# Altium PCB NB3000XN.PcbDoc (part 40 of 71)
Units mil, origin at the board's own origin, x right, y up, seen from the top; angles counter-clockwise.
Board outline 9527.56 x 6929.77 mil, 6 copper layers (Top Layer, GND+SHIELD, MidLayer1, MidLayer2, P2 - 3V3+5V0, Bottom Layer), stack 62.375 mil thick; 832 components, 1027 nets, 4655 pads, 4981 vias.
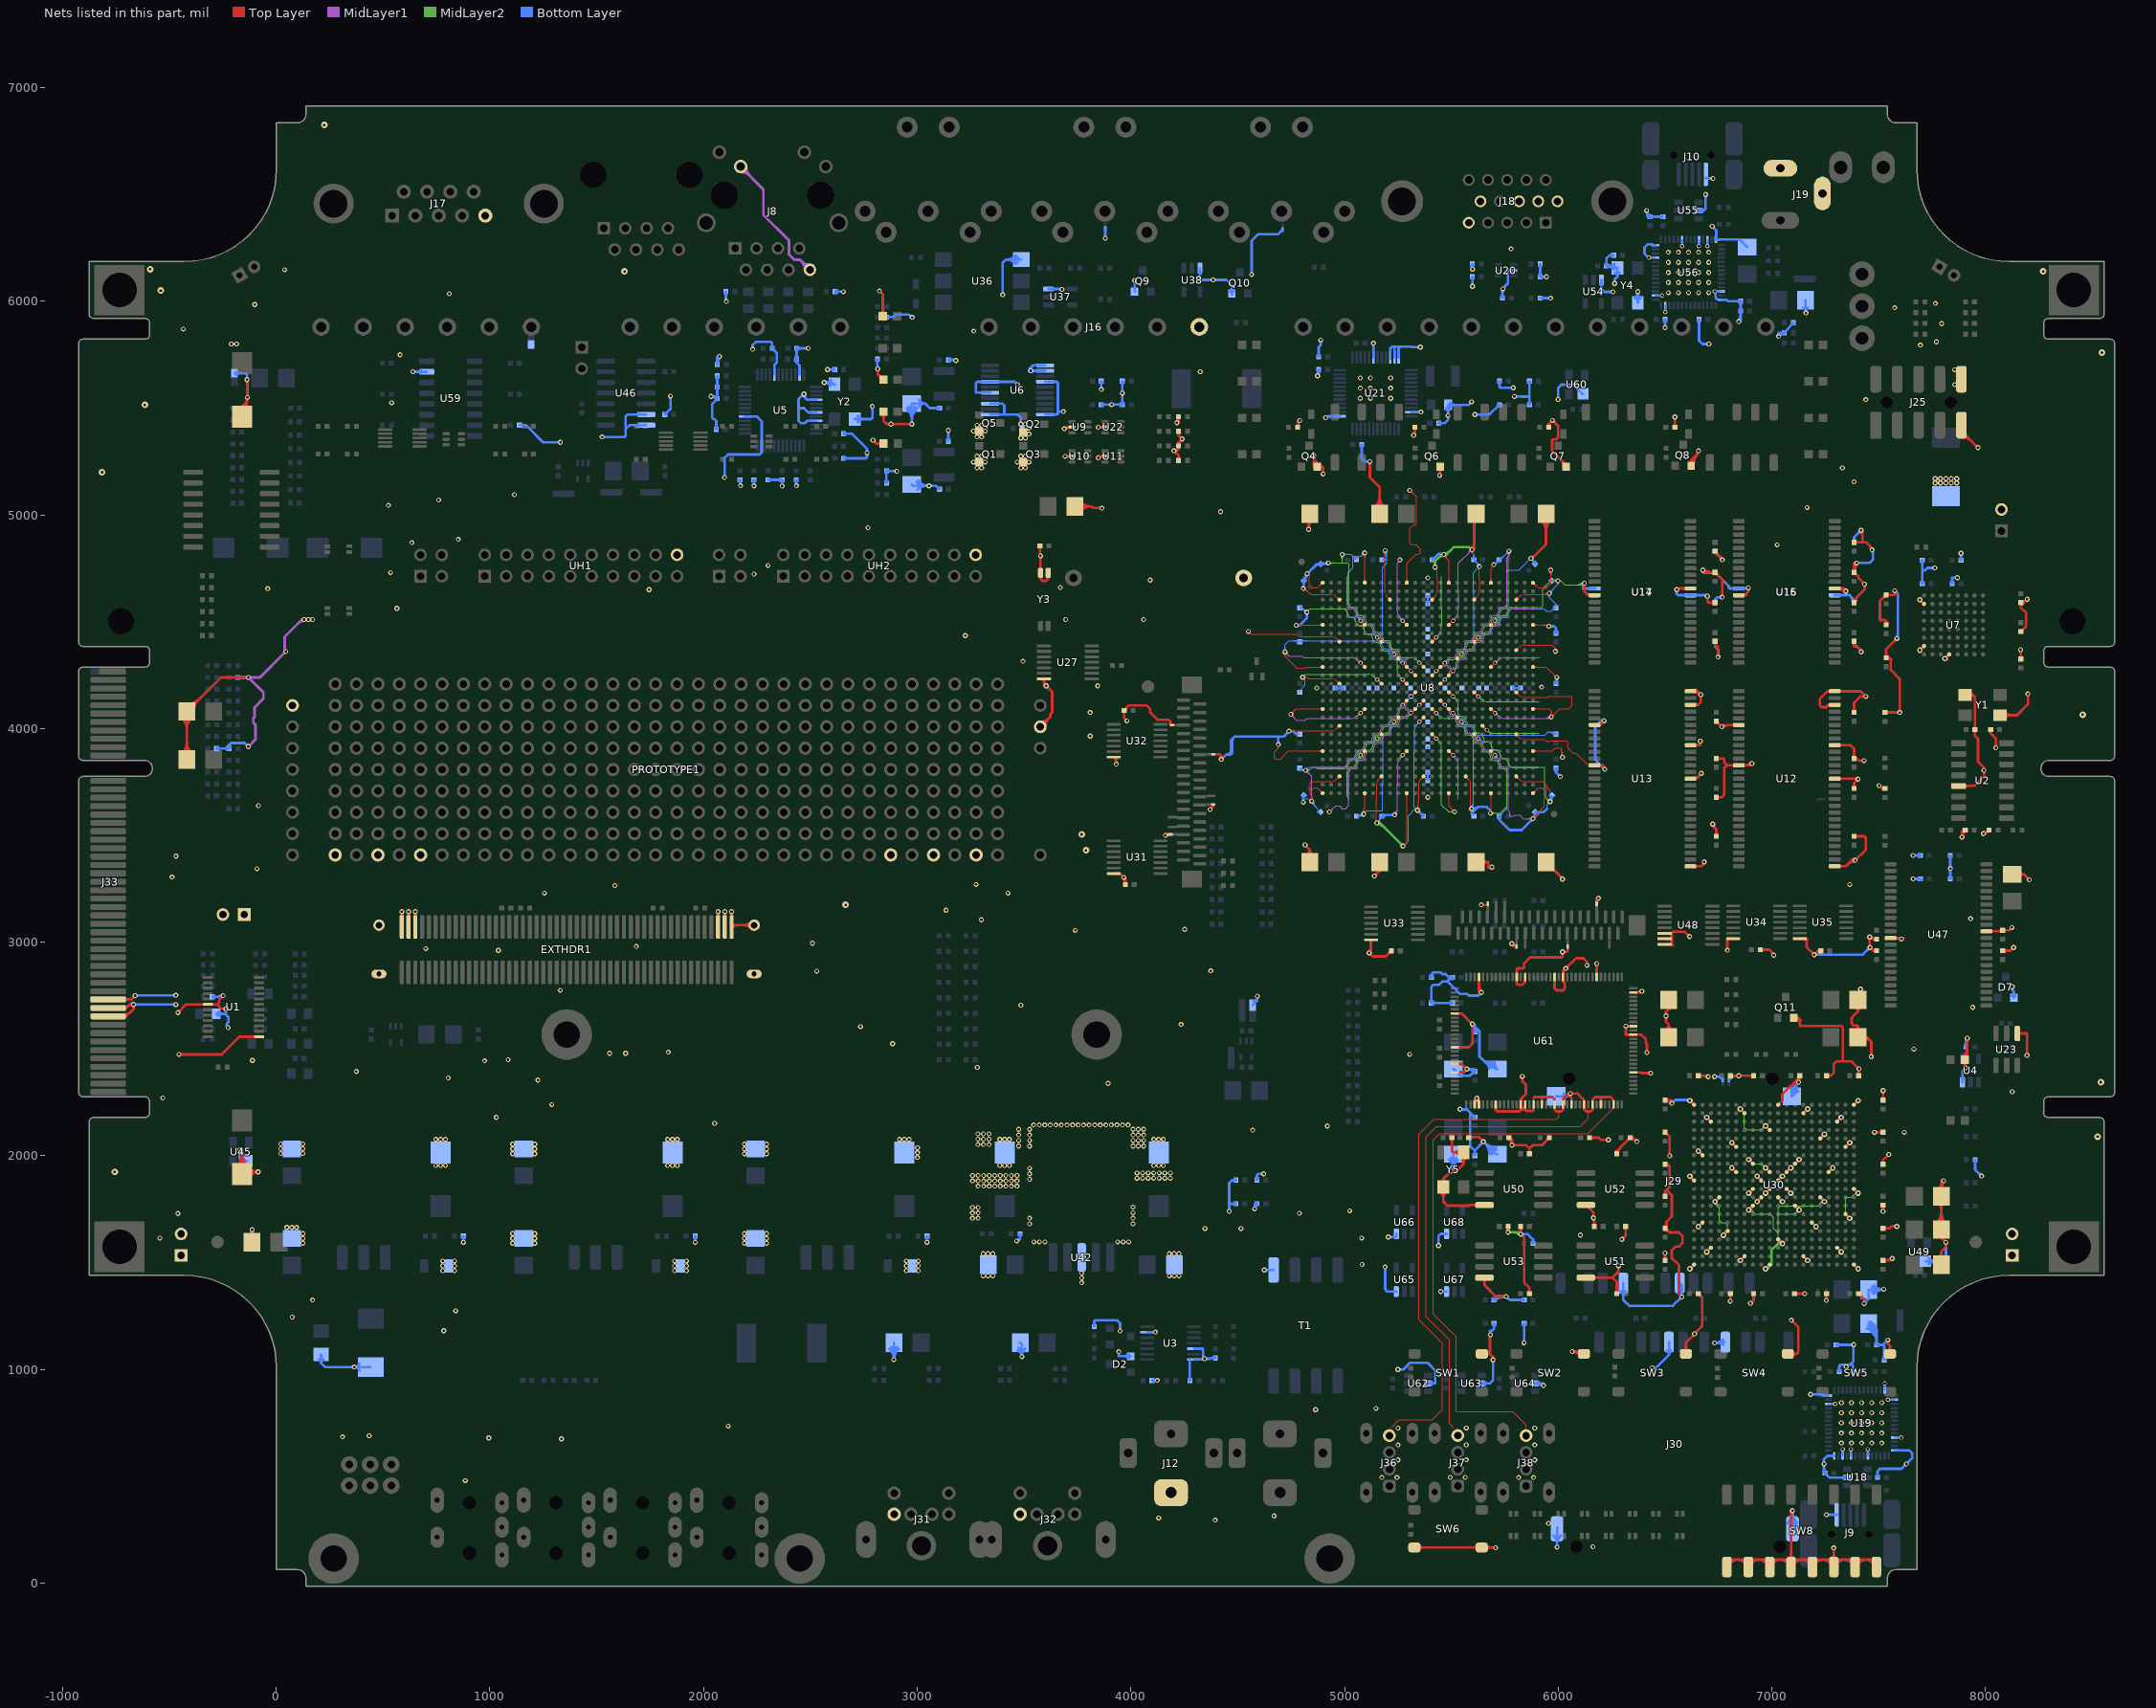
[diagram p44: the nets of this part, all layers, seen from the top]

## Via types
v1: diameter 23, hole 11.81, Top Layer to Bottom Layer, 3672 vias
v2: diameter 26, hole 11.81, Top Layer to Bottom Layer, 461 vias
v3: diameter 19, hole 11.81, Top Layer to Bottom Layer, tented both sides, 396 vias
v4: diameter 23.62, hole 11.81, Top Layer to Bottom Layer, 288 vias
v5: diameter 20, hole 11.81, Top Layer to Bottom Layer, 91 vias
v6: diameter 23, hole 11.81, Top Layer to Bottom Layer, tented both sides, 50 vias
v7: diameter 31, hole 11.81, Top Layer to Bottom Layer, 15 vias
v8: diameter 27.56, hole 11.81, Top Layer to Bottom Layer, tented both sides, 4 vias
v9: diameter 29, hole 11.81, Top Layer to Bottom Layer, 3 vias
v10: diameter 21, hole 11.81, Top Layer to Bottom Layer, 1 vias

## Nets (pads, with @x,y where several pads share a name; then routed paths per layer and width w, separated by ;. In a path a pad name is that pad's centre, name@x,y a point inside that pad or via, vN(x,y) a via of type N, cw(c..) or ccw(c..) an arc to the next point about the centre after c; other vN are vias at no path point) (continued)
GND: BT1.2 C1.2 C2.2 C3.2 C4.2 C7.2 C13.2 C18.2 C20.2 C21.2 C33.2 C34.2 C35.2 C36.2 C37.1 C39.1 C40.2 C41.1 C42.1 C43.2 C44.2 C45.1 C46.1 C47.1 C48.1 C49.2 C50.1 C51.1 C52.1 C53.1 C54.1 C55.2 C56.2 C57.2 C58.2 C59.2 C60.2 C61.2 C62.2 C63.2 C64.2 C65.2 C66.2 C67.2 C68.2 C69.2 C70.2 C71.2 C72.2 C73.2 C74.2 C75.2 C76.2 C77.2 C78.2 C79.2 C80.2 C81.2 C82.2 C83.2 C84.2 C85.2 C86.2 C87.2 C88.1 C89.2 C90.1 C91.1 C92.1 C93.2 C94.2 C95.2 C96.2 C98.2 C99.1 C100.2 C115.2 C116.2 C121.1 C122.1 C123.1 C124.1 C125.1 C126.2 C127.2 C128.2 C129.2 C130.2 C131.2 C132.2 C133.2 C134.2 C135.2 C136.2 C137.2 C138.2 C139.2 C140.2 C141.2 C151.2 C152.1 C153.2 C154.2 C155.2 C156.2 C157.1 C158.2 C159.1 C160.2 C161.1 C162.2 C163.1 C164.2 C165.1 C166.2 C167.2 C168.2 C169.1 C170.1 C171.2 C172.1 C173.1 C174.1 C175.2 C176.2 C177.2 C184.2 C185.2 C187.2 C189.2 C190.2 C191.2 C192.2 C193.2 C194.2 C195.2 C196.2 C197.2 C198.2 C199.2 C200.2 C201.2 C202.2 C203.2 C215.2 C216.2 C217.2 C218.2 C219.2 C220.2 C221.2 C222.2 C223.2 C224.2 C225.2 C226.2 C227.2 C228.2 C229.2 C231.2 C232.2 C233.2 C234.2 C235.2 C236.2 C237.2 C238.2 C239.2 C240.2 C241.2 C242.2 C243.2 C244.2 C245.2 C246.2 C247.2 C248.2 C249.2 C250.2 C251.2 C252.2 C253.2 C254.2 C255.2 C256.2 C257.2 C258.2 C259.2 C260.2 C265.2 C266.2 C267.2 C268.2 C269.2 C270.2 C271.2 C272.2 C273.2 C274.2 C275.2 C276.2 C277.2 C278.2 C279.2 C291.2 C292.2 C293.2 C294.2 C295.2 C296.2 C297.2 C298.2 C299.2 C300.2 C301.2 C302.2 C303.2 C304.2 C305.2 C307.2 C308.2 C309.2 C310.2 C311.2 C312.2 C313.2 C314.2 C315.2 C316.2 C317.2 C318.2 C319.2 C320.2 C321.2 C322.2 C323.2 C324.2 C325.2 C326.2 C327.2 C328.2 C329.2 C330.2 C331.2 C332.2 C333.2 C334.2 C335.2 C336.2 C337.2 C338.2 C339.2 C340.2 C341.2 C342.2 D2.1 D7.1 D10.1 EXTHDR1.1 EXTHDR1.3 EXTHDR1.5 EXTHDR1.95 EXTHDR1.97 EXTHDR1.99 EXTHDR1.MH1 EXTHDR1.MH2 EXTHDR1.MH3 EXTHDR1.MH4 J1.1 J1.2 J2.1 J2.2 J3.1 J3.2 J8.8 J8.10 J9.5 J10.5 J12.1 J16.6 J17.5 J18.5 J18.6 J18.7 J18.8 J18.10 J19.2 J19.3 J24.2 J25.9 J25.10 J29.3 J29.6 J29.GND1 J29.GND2 J30.3 J30.6 J30.GND1 J30.GND2 J31.3 J32.3 J33.A38 J33.A39 J33.A40 J33.B38 J36.4 J37.4 J38.4 LED1.2 LED4.2 LED5.2 LED6.2 LED7.2 NT1.2 NT4.2 NT5.2 NT7.2 NT11.2 NT28.2 NT29.2 NT30.2 NT31.2 NT38.2 NT39.2 NT40.2 NT41.2 NT44.1 NT47.1 NT48.1 PROTOTYPE1.1 PROTOTYPE1.3 PROTOTYPE1.5 PROTOTYPE1.27 PROTOTYPE1.29 PROTOTYPE1.31 Q1.3 Q2.3 Q3.3 Q4.3 Q5.3 Q6.3 Q7.3 Q8.3 Q9.3 Q10.3 Q11.3 R30.2 R34.2 R36.2 R38.1 R41.2 R42.2 R43.2 R44.2 R45.2 R46.2 R47.2 R51.2 R52.2 R56.1 R60.1 R61.2 R64.1 R65.2 R91.1 R93.1 R95.1 R97.1 R109.2 R111.2 R116.1 R117.2 R118.1 R119.2 R120.1 R121.1 R122.1 R124.1 R126.1 R128.1 R130.1 R155.1 R157.1 R160.2 R163.1 R202.2 R204.2 R206.2 R208.2 R246.2 R257.2 R258.2 R259.2 SW1.3 SW2.3 SW3.3 SW4.3 SW5.3 SW6.3 SW6.4 SW8.1 SW8.2 SW8.3 SW8.4 SW8.5 SW8.6 SW8.7 SW8.8 T1.1 TP1.1 TP8.1 U1.6 U1.13 U2.5 U3.5 U3.7 U3.13 U4.3 U5.11 U5.17 U5.29 U5.35 U5.40 U5.43 U5.45 U6.1 U6.2 U6.4 U6.10 U6.11 U6.13 U6.15 U6.17 U7.E8 U7.H2 U7.H7 U8.A1 U8.A6 U8.A11 U8.A16 U8.A21 U8.A26 U8.AA1 U8.AA6 U8.AA11 U8.AA16 U8.AA21 U8.AA26 U8.AD3 U8.AD8 U8.AD13 U8.AD18 U8.AD24 U8.AF1 U8.AF6 U8.AF11 U8.AF16 U8.AF21 U8.AF26 U8.C3 U8.C9 U8.C14 U8.C19 U8.C24 U8.F1 U8.F6 U8.F11 U8.F16 U8.F21 U8.F26 U8.H3 U8.H8 U8.H14 U8.H19 U8.J24 U8.K10 U8.K17 U8.L1 U8.L6 U8.L11 U8.L13 U8.L15 U8.L21 U8.L26 U8.M12 U8.M14 U8.M16 U8.N3 U8.N8 U8.N11 U8.N15 U8.P12 U8.P16 U8.P19 U8.P24 U8.R11 U8.R13 U8.R15 U8.T1 U8.T6 U8.T12 U8.T14 U8.T16 U8.T21 U8.T26 U8.U10 U8.U13 U8.U17 U8.V3 U8.V20 U8.W8 U8.W14 U8.W19 U8.W24 U9.2 U10.2 U11.2 U12.6 U12.12 U12.28 U12.41 U12.46 U12.52 U12.54 U13.6 U13.12 U13.28 U13.41 U13.46 U13.52 U13.54 U14.12 U14.34 U15.12 U15.34 U16.12 U16.34 U17.12 U17.34 U18.2 U19.6 U19.10 U19.12 U19.14 U19.26 U19.28 U19.41 U19.44 U19.53 U19.56 U20.2 U21.11 U21.25 U21.42 U21.46 U21.47 U21.48 U22.2 U23.1 U27.7 U30.A1 U30.A11 U30.A20 U30.B6 U30.B14 U30.C3 U30.C18 U30.D9 U30.E5 U30.E12 U30.F15 U30.G2 U30.G19 U30.H8 U30.H13 U30.J9 U30.J11 U30.K1 U30.K10 U30.K12 U30.K17 U30.L4 U30.L9 U30.L11 U30.L20 U30.M10 U30.M12 U30.N8 U30.N11 U30.N13 U30.P2 U30.P19 U30.R6 U30.R9 U30.T16 U30.U12 U30.V3 U30.V18 U30.W7 U30.W15 U30.Y1 U30.Y10 U30.Y20 U31.7 U32.7 U33.7 U34.7 U35.7 U36.4 U37.3 U38.3 U42.3 U45.1 U46.6 U46.7 U47.12 U47.34 U48.6 U48.7 U48.8 U49.1 U50.4 U51.4 U52.4 U53.4 U54.3 U55.2 U56.6 U56.10 U56.12 U56.14 U56.26 U56.28 U56.41 U56.44 U56.53 U56.56 U59.15 U60.1 U61.3 U61.4 U61.8 U61.14 U61.15 U61.17 U61.19 U61.22 U61.24 U61.26 U61.29 U61.31 U61.33 U61.36 U61.44 U61.53 U61.55 U61.63 U61.71 U61.79 U61.81 U61.88 U61.90 U61.99 U61.109 U61.117 U61.121 U61.123 U62.2 U63.2 U64.2 U65.3 U66.3 U67.3 U68.3 UH1.20 UH2.20 Y1.2 Y1.4 Y2.2 Y2.4 Y3.2 Y3.3 Y4.2 Y4.4 Y5.2 Y5.4 | length 134362.1
  Top Layer w4: v1(4550,4455) 4563.13,4441.87 4760,4441.87 4777.33,4441.87 4788.8,4430.4 4793.8,4430.4 4806,4430.4 4860,4430.4 4870,4430.4 4936.73,4430.4 cw(c4936.73,4391.72) 4964.08,4419.07 ; v1(4690.19,3925.04) 4690.19,3909.71 4672.52,3892.04 4672.52,3864.71 4678.86,3858.37 4701.52,3858.37 4737.87,3894.72 ; v1@4715.28,4350.94 cw(c4705.54,4338.69) 4721.19,4338.69 ; v1(4721.19,4358.37) 4721.19,4338.69 ; v1@4727.1,4350.94 ccw(c4736.84,4338.69) 4721.19,4338.69 ; v1(4740.19,3987.71) 4741.45,3988.97 4855.26,3988.97 4860,3988.97 4870,3988.97 4936.73,3988.97 ccw(c4936.73,4027.65) 4964.08,4000.3 ; v1(4748.52,4066.71) 4773.39,4091.57 4860,4091.57 4870,4091.57 U8.T1@4897.87,4091.57 ; v1@4748.52,4072.21 ccw(c4748.52,4085.49) 4757.91,4076.1 ccw(c4767.3,4066.71) v1@4754.02,4066.71 ; v1@4748.52,4076.21 ccw(c4748.52,4099.14) 4764.74,4082.93 ccw(c4780.96,4066.71) v1@4758.02,4066.71 ; v1(4773.52,4483.37) 4775.43,4485.28 4860,4485.28 4870,4485.28 U8.F1@4897.87,4485.28 ; 4774.72,3894.72 4737.87,3894.72 ; v1@4777.41,4479.49 cw(c4791.39,4465.51) 4791.39,4485.28 ; v1@4780.24,4476.66 cw(c4801.05,4455.85) 4801.05,4485.28 ; v1@4780.24,4490.09 ccw(c4791.87,4501.72) 4791.87,4485.28 ; v1@4807,4645.5 cw(c4807,4604.3) 4836.13,4633.43 ; v1@4807,4649.5 cw(c4807,4617.96) 4829.3,4640.26 ; v1@4807,4653.5 cw(c4807,4631.62) 4822.47,4647.09 ; v1(4807,4655) 4808.85,4656.85 4812.71,4656.85 4842.19,4627.37 4842.19,4627.25 4855.26,4627.25 4860,4627.25 4870,4627.25 4936.73,4627.25 ; v1@4810.69,4233.55 v1(4803.86,4240.37) 4823.17,4240.37 4830,4233.55 4855.26,4233.55 4860,4233.55 4870,4233.55 4936.73,4233.55 cw(c4936.73,4194.87) 4964.08,4222.22 ; v1(4825.19,4725.04) 4835,4715.23 4835,4670 4846.74,4658.26 4856.86,4658.26 ; v1@4839.47,3666.76 ccw(c4823.26,3682.98) 4846.19,3682.98 ccw(c4869.13,3682.98) v1@4852.91,3666.76 ; 4840,3715 4840,3718.47 ; v1@4842.3,3663.93 ccw(c4832.91,3673.32) 4846.19,3673.32 ccw(c4859.47,3673.32) v1@4850.08,3663.93 ; v1(4846.19,3660.04) 4846.19,3683.81 4840,3690 4840,3718.47 ; 4857.99,4658.26 ccw(c4857.99,4696.94) 4885.34,4669.59 ; U8.AF1@4890.53,3697.87 ccw(c4872.8,3697.87) 4885.34,3710.41 ; U8.A1@4890.53,4682.13 cw(c4872.8,4682.13) 4885.34,4669.59 ; U8.AA1@4892.57,3889.42 ccw(c4879.77,3876.62) 4879.77,3894.72 ccw(c4879.77,3912.83) U8.AA1@4892.57,3900.03 ; U8.T1@4892.57,4086.27 ccw(c4879.77,4073.47) 4879.77,4091.57 ccw(c4879.77,4109.68) U8.T1@4892.57,4096.88 ; U8.L1@4892.57,4283.12 ccw(c4879.77,4270.32) 4879.77,4288.43 ccw(c4879.77,4306.53) U8.L1@4892.57,4293.73 ; U8.F1@4892.57,4479.97 ccw(c4879.77,4467.17) 4879.77,4485.28 ccw(c4879.77,4503.38) U8.F1@4892.57,4490.58 ; U8.AA1@4892.68,3889.53 ccw(c4880.15,3877) 4880.15,3894.72 ccw(c4880.15,3912.45) U8.AA1@4892.68,3899.92 ; U8.T1@4892.68,4086.38 ccw(c4880.15,4073.85) 4880.15,4091.57 ccw(c4880.15,4109.3) U8.T1@4892.68,4096.77 ; U8.L1@4892.68,4283.23 ccw(c4880.15,4270.7) 4880.15,4288.43 ccw(c4880.15,4306.15) U8.L1@4892.68,4293.62 ; U8.F1@4892.68,4480.08 ccw(c4880.15,4467.55) 4880.15,4485.28 ccw(c4880.15,4503) U8.F1@4892.68,4490.47 ; U8.AF1@4897.87,3705.22 cw(c4897.87,3722.94) 4885.34,3710.41 ; U8.AA1@4897.87,3894.72 4870,3894.72 4860,3894.72 4737.87,3894.72 ; U8.L1@4897.87,4288.43 4870,4288.43 4860,4288.43 4823.43,4288.43 4817.54,4282.54 4777.34,4282.54 4721.19,4338.69 ; U8.A1@4897.87,4674.78 ccw(c4897.87,4657.06) 4885.34,4669.59 ; U8.AD3@4969.27,3776.61 cw(c4951.55,3776.61) 4964.08,3764.08 ; U8.V3@4969.27,4012.83 cw(c4951.55,4012.83) 4964.08,4000.3 ; U8.N3@4969.27,4209.69 ccw(c4951.55,4209.69) 4964.08,4222.22 ; U8.H3@4969.27,4406.54 ccw(c4951.55,4406.54) 4964.08,4419.07 ; U8.C3@4969.27,4603.39 ccw(c4951.55,4603.39) 4964.08,4615.92 ; U8.AD3@4976.61,3769.27 ccw(c4976.61,3751.55) 4964.08,3764.08 ; U8.V3@4976.61,4005.49 ccw(c4976.61,3987.77) 4964.08,4000.3 ; U8.N3@4976.61,4217.03 cw(c4976.61,4234.75) 4964.08,4222.22 ; U8.H3@4976.61,4413.88 cw(c4976.61,4431.6) 4964.08,4419.07 ; U8.C3@4976.61,4610.73 cw(c4976.61,4628.45) 4964.08,4615.92 ; v3(5075.04,3875.04) U8.AA6@5094.72,3894.72 ; v3(5075.04,4071.89) U8.T6@5094.72,4091.57 ; v3(5075.04,4308.11) U8.L6@5094.72,4288.43 ; v3(5075.04,4504.96) U8.F6@5094.72,4485.28 ; v1@5083.47,3606.76 ccw(c5067.71,3622.52) 5090,3622.52 ; v1@5086.3,3603.93 ccw(c5077.37,3612.86) 5090,3612.86 ; U8.AA6@5087.22,3894.72 cw(c5069.12,3894.72) 5081.92,3881.92 cw(c5094.72,3869.12) U8.AA6@5094.72,3887.22 ; U8.T6@5087.22,4091.57 cw(c5069.12,4091.57) 5081.92,4078.77 cw(c5094.72,4065.97) U8.T6@5094.72,4084.07 ; U8.L6@5087.22,4288.43 ccw(c5069.12,4288.43) 5081.92,4301.23 ccw(c5094.72,4314.03) U8.L6@5094.72,4295.93 ; U8.F6@5087.22,4485.28 ccw(c5069.12,4485.28) 5081.92,4498.08 ccw(c5094.72,4510.88) U8.F6@5094.72,4492.78 ; U8.AA6@5087.38,3894.72 cw(c5069.66,3894.72) 5082.19,3882.19 cw(c5094.72,3869.66) U8.AA6@5094.72,3887.38 ; U8.T6@5087.38,4091.57 cw(c5069.66,4091.57) 5082.19,4079.04 cw(c5094.72,4066.51) U8.T6@5094.72,4084.23 ; U8.L6@5087.38,4288.43 ccw(c5069.66,4288.43) 5082.19,4300.96 ccw(c5094.72,4313.49) U8.L6@5094.72,4295.77 ; U8.F6@5087.38,4485.28 ccw(c5069.66,4485.28) 5082.19,4497.81 ccw(c5094.72,4510.34) U8.F6@5094.72,4492.62 ; v1@5087.81,4815.66 cw(c5071.11,4798.96) 5094.72,4798.96 ; U8.AF6@5089.42,3692.57 cw(c5076.62,3679.77) 5094.72,3679.77 cw(c5112.83,3679.77) U8.AF6@5100.03,3692.57 ; U8.A6@5089.42,4687.43 ccw(c5076.62,4700.23) 5094.72,4700.23 ccw(c5112.83,4700.23) U8.A6@5100.03,4687.43 ; U8.AF6@5089.53,3692.68 cw(c5077,3680.15) 5094.72,3680.15 cw(c5112.45,3680.15) U8.AF6@5099.92,3692.68 ; U8.A6@5089.53,4687.32 ccw(c5077,4699.85) 5094.72,4699.85 ccw(c5112.45,4699.85) U8.A6@5099.92,4687.32 ; 5090,3613.78 ccw(c5103.93,3613.78) v1@5094.08,3603.93 ; 5090,3623.43 ccw(c5113.58,3623.43) v1@5096.91,3606.76 ; v1@5090.64,4818.49 cw(c5080.76,4808.61) 5094.72,4808.61 ; v1(5094.52,4822.37) 5094.72,4822.17 5094.72,4724.74 5094.72,4720 5094.72,4710 U8.A6@5094.72,4682.13 ; v1@5094.72,3604.57 v1(5090.19,3600.04) 5090,3600.23 5090,3625 5094.72,3629.72 5094.72,3660 5094.72,3670 U8.AF6@5094.72,3697.87 ; 5094.72,4799.92 cw(c5116.98,4799.92) v1@5101.24,4815.66 ; 5094.72,4809.58 cw(c5107.32,4809.58) v1@5098.41,4818.49 ; U33.7@5123.52,3011.46 U33.7@5125,3011.46 ; v1(5150.86,3558.37) 5149.6,3559.63 5149.6,3655.26 5149.6,3660 5149.6,3670 5149.6,3736.73 cw(c5188.28,3736.73) 5160.93,3764.08 ; v3(5153.78,3953.78) U8.W8@5173.46,3973.46 ; v3(5153.78,4229.37) U8.N8@5173.46,4209.69 ; v3(5153.78,4426.22) U8.H8@5173.46,4406.54 ; U8.W8@5165.96,3973.46 cw(c5147.86,3973.46) 5160.66,3960.66 cw(c5173.46,3947.86) U8.W8@5173.46,3965.96 ; U8.N8@5165.96,4209.69 ccw(c5147.86,4209.69) 5160.66,4222.49 ccw(c5173.46,4235.29) U8.N8@5173.46,4217.19 ; U8.H8@5165.96,4406.54 ccw(c5147.86,4406.54) 5160.66,4419.34 ccw(c5173.46,4432.14) U8.H8@5173.46,4414.04 ; U8.AD8@5166.12,3776.61 cw(c5148.4,3776.61) 5160.93,3764.08 ; U8.W8@5166.12,3973.46 cw(c5148.4,3973.46) 5160.93,3960.93 cw(c5173.46,3948.4) U8.W8@5173.46,3966.12 ; U8.N8@5166.12,4209.69 ccw(c5148.4,4209.69) 5160.93,4222.22 ccw(c5173.46,4234.75) U8.N8@5173.46,4217.03 ; U8.H8@5166.12,4406.54 ccw(c5148.4,4406.54) 5160.93,4419.07 ccw(c5173.46,4431.6) U8.H8@5173.46,4413.88 ; U8.AD8@5173.46,3769.27 ccw(c5173.46,3751.55) 5160.93,3764.08 ; v1(5190.19,4833.37) 5190.19,4825.04 5188.97,4823.82 5188.97,4724.74 5188.97,4720 5188.97,4710 5188.97,4643.27 ccw(c5227.65,4643.27) 5200.3,4615.92 ; U8.C9@5205.49,4603.39 ccw(c5187.77,4603.39) 5200.3,4615.92 ; U8.C9@5212.83,4610.73 cw(c5212.83,4628.45) 5200.3,4615.92 ; v3(5232.52,4032.52) U8.U10@5252.2,4052.2 ; v3(5232.52,4347.48) U8.K10@5252.2,4327.8 ; U8.U10@5244.7,4052.2 cw(c5226.6,4052.2) 5239.4,4039.4 cw(c5252.2,4026.6) U8.U10@5252.2,4044.7 ; U8.K10@5244.7,4327.8 ccw(c5226.6,4327.8) 5239.4,4340.6 ccw(c5252.2,4353.4) U8.K10@5252.2,4335.3 ; U8.U10@5244.86,4052.2 cw(c5227.14,4052.2) 5239.67,4039.67 cw(c5252.2,4027.14) U8.U10@5252.2,4044.86 ; U8.K10@5244.86,4327.8 ccw(c5227.14,4327.8) 5239.67,4340.33 ccw(c5252.2,4352.86) U8.K10@5252.2,4335.14 ; v3(5271.89,3875.04) U8.AA11@5291.57,3894.72 ; v3(5271.89,4111.26) U8.R11@5291.57,4130.94 ; v3(5271.89,4229.37) U8.N11@5291.57,4209.69 ; v3(5271.89,4308.11) U8.L11@5291.57,4288.43 ; v3(5271.89,4504.96) U8.F11@5291.57,4485.28 ; v1(5273.52,3450.04) 5279.19,3450.04 5291.58,3462.43 ; v1@5275.34,3455.23 ccw(c5279.06,3465.92) 5287.07,3457.92 ; v1@5276.65,3459.01 ccw(c5281.39,3472.61) 5291.57,3462.43 ; v1@5283.02,3450.04 cw(c5292.28,3450.04) 5285.74,3456.59 ; U8.AA11@5284.07,3894.72 cw(c5265.97,3894.72) 5278.77,3881.92 cw(c5291.57,3869.12) U8.AA11@5291.57,3887.22 ; U8.R11@5284.07,4130.94 cw(c5265.97,4130.94) 5278.77,4118.14 cw(c5291.57,4105.34) U8.R11@5291.57,4123.44 ; U8.N11@5284.07,4209.69 ccw(c5265.97,4209.68) 5278.77,4222.49 ccw(c5291.57,4235.29) U8.N11@5291.57,4217.19 ; U8.L11@5284.07,4288.43 ccw(c5265.97,4288.43) 5278.77,4301.23 ccw(c5291.57,4314.03) U8.L11@5291.57,4295.93 ; U8.F11@5284.07,4485.28 ccw(c5265.97,4485.28) 5278.77,4498.08 ccw(c5291.57,4510.88) U8.F11@5291.57,4492.78 ; U8.AA11@5284.23,3894.72 cw(c5266.51,3894.72) 5279.04,3882.19 cw(c5291.57,3869.66) U8.AA11@5291.57,3887.38 ; U8.R11@5284.23,4130.94 cw(c5266.51,4130.94) 5279.04,4118.41 cw(c5291.57,4105.88) U8.R11@5291.57,4123.6 ; U8.N11@5284.23,4209.69 ccw(c5266.51,4209.68) 5279.04,4222.22 ccw(c5291.57,4234.75) U8.N11@5291.57,4217.03 ; U8.L11@5284.23,4288.43 ccw(c5266.51,4288.43) 5279.04,4300.96 ccw(c5291.57,4313.49) U8.L11@5291.57,4295.77 ; U8.F11@5284.23,4485.28 ccw(c5266.51,4485.28) 5279.04,4497.81 ccw(c5291.57,4510.34) U8.F11@5291.57,4492.62 ; U8.AF11@5286.27,3692.57 cw(c5273.47,3679.77) 5291.57,3679.77 cw(c5309.68,3679.77) U8.AF11@5296.88,3692.57 ; U8.A11@5286.27,4687.43 ccw(c5273.47,4700.23) 5291.57,4700.23 ccw(c5309.68,4700.23) U8.A11@5296.88,4687.43 ; U8.AF11@5286.38,3692.68 cw(c5273.85,3680.15) 5291.57,3680.15 cw(c5309.3,3680.15) U8.AF11@5296.77,3692.68 ; U8.A11@5286.38,4687.32 ccw(c5273.85,4699.85) 5291.57,4699.85 ccw(c5309.3,4699.85) U8.A11@5296.77,4687.32 ; U8.AF11@5291.57,3697.87 5291.57,3670 5291.57,3660 5291.57,3655.26 5291.58,3462.43 ; U8.A11@5291.57,4682.13 5291.57,4710 5291.57,4720 5291.57,4772.78 5333.8,4815 5347.02,4815 5355.5,4823.48 5355.5,4838.42 5351.96,4841.96 5345,4848.92 5333.92,4860 5315,4860 5306.02,4868.98 5306.02,4936.02 5325.69,4955.69 5332.17,4955.69 5336.48,4960 5336.48,5083.52 v4(5305,5115) ; v4@5305,5105.19 cw(c5305,5081.5) 5321.75,5098.25 cw(c5338.5,5115) v4@5314.81,5115 ; v4@5305,5109.19 cw(c5305,5095.16) 5314.92,5105.08 cw(c5324.84,5115) v4@5310.81,5115 ; v3(5311.26,4071.89) U8.T12@5330.94,4091.57 ; v3(5311.26,4150.63) U8.P12@5330.94,4170.31 ; v3(5311.26,4268.74) U8.M12@5330.94,4249.06 ; U8.T12@5323.44,4091.57 cw(c5305.34,4091.57) 5318.14,4078.77 cw(c5330.94,4065.97) U8.T12@5330.94,4084.07 ; U8.P12@5323.44,4170.32 cw(c5305.34,4170.32) 5318.14,4157.51 cw(c5330.94,4144.71) U8.P12@5330.94,4162.81 ; U8.M12@5323.44,4249.06 ccw(c5305.34,4249.06) 5318.14,4261.86 ccw(c5330.94,4274.66) U8.M12@5330.94,4256.56 ; U8.T12@5323.6,4091.57 cw(c5305.88,4091.57) 5318.41,4079.04 cw(c5330.94,4066.51) U8.T12@5330.94,4084.23 ; U8.P12@5323.6,4170.32 cw(c5305.88,4170.32) 5318.41,4157.78 cw(c5330.94,4145.25) U8.P12@5330.94,4162.97 ; U8.M12@5323.6,4249.06 ccw(c5305.88,4249.06) 5318.41,4261.59 ccw(c5330.94,4274.12) U8.M12@5330.94,4256.4 ; v1@5335.02,3624.97 ccw(c5310.24,3651.37) 5346.45,3651.37 ; v1@5337.76,3622.05 ccw(c5318.91,3642.13) 5346.45,3642.13 ; v1@5340.5,3619.13 ccw(c5327.58,3632.89) 5346.45,3632.89 ; v1(5341.52,3618.04) 5346.45,3622.97 5346.45,3651.37 ; 5346.45,3629.08 ccw(c5352.56,3629.08) v1@5348.24,3624.76 ; v3(5350.63,4032.52) U8.U13@5370.31,4052.2 ; v3(5350.63,4111.26) U8.R13@5370.31,4130.94 ; v3(5350.63,4308.11) U8.L13@5370.31,4288.43 ; U8.U13@5362.81,4052.2 cw(c5344.71,4052.2) 5357.51,4039.4 cw(c5370.31,4026.6) U8.U13@5370.31,4044.7 ; U8.R13@5362.81,4130.94 cw(c5344.71,4130.94) 5357.51,4118.14 cw(c5370.31,4105.34) U8.R13@5370.31,4123.44 ; U8.L13@5362.81,4288.43 ccw(c5344.71,4288.43) 5357.51,4301.23 ccw(c5370.31,4314.03) U8.L13@5370.31,4295.93 ; U8.AD13@5362.97,3776.61 cw(c5345.25,3776.61) 5357.78,3764.08 ; U8.U13@5362.97,4052.2 cw(c5345.25,4052.2) 5357.78,4039.67 cw(c5370.31,4027.14) U8.U13@5370.31,4044.86 ; U8.R13@5362.97,4130.94 cw(c5345.25,4130.94) 5357.78,4118.41 cw(c5370.31,4105.88) U8.R13@5370.31,4123.6 ; U8.L13@5362.97,4288.43 ccw(c5345.25,4288.43) 5357.78,4300.96 ccw(c5370.31,4313.49) U8.L13@5370.31,4295.77 ; U8.AD13@5370.31,3769.27 ccw(c5370.31,3751.55) 5357.78,3764.08 ; U8.W14@5409.69,3965.96 cw(c5409.69,3947.86) 5422.49,3960.66 cw(c5435.29,3973.46) U8.W14@5417.19,3973.46 ; U8.W14@5409.69,3966.12 cw(c5409.69,3948.4) 5422.22,3960.93 cw(c5434.75,3973.46) U8.W14@5417.03,3973.46 ; U8.W14@5409.69,3973.46 v3(5429.37,3953.78) ; U8.T14@5409.69,4084.07 cw(c5409.69,4065.97) 5422.49,4078.77 cw(c5435.29,4091.57) U8.T14@5417.19,4091.57 ; U8.T14@5409.69,4084.23 cw(c5409.69,4066.51) 5422.22,4079.04 cw(c5434.75,4091.57) U8.T14@5417.03,4091.57 ; U8.T14@5409.69,4091.57 v3(5429.37,4071.89) ; U8.M14@5409.69,4249.06 v3(5429.37,4268.74) ; U8.M14@5409.69,4256.4 ccw(c5409.69,4274.12) 5422.22,4261.59 ccw(c5434.75,4249.06) U8.M14@5417.03,4249.06 ; U8.M14@5409.69,4256.56 ccw(c5409.69,4274.66) 5422.49,4261.86 ccw(c5435.29,4249.06) U8.M14@5417.19,4249.06 ; U8.H14@5409.69,4406.54 v3(5429.37,4426.22) ; U8.H14@5409.69,4413.88 ccw(c5409.69,4431.6) 5422.22,4419.07 ccw(c5434.75,4406.54) U8.H14@5417.03,4406.54 ; U8.H14@5409.69,4414.04 ccw(c5409.69,4432.14) 5422.49,4419.34 ccw(c5435.29,4406.54) U8.H14@5417.19,4406.54 ; U8.C14@5409.69,4610.73 ccw(c5409.69,4628.45) 5422.22,4615.92 ; U8.C14@5417.03,4603.39 cw(c5434.75,4603.39) 5422.22,4615.92 ; v1(5423.52,4755.71) 5433.55,4745.68 5433.55,4720 5433.55,4710 5433.55,4643.27 cw(c5394.87,4643.27) 5422.22,4615.92 ; 5433.55,4724.74 5433.55,4725.04 ; U8.R15@5449.06,4123.44 cw(c5449.06,4105.34) 5461.86,4118.14 cw(c5474.66,4130.94) U8.R15@5456.56,4130.94 ; U8.R15@5449.06,4123.6 cw(c5449.06,4105.88) 5461.59,4118.41 cw(c5474.12,4130.94) U8.R15@5456.4,4130.94 ; U8.R15@5449.06,4130.94 v3(5468.74,4111.26) ; U8.N15@5449.06,4209.69 v3(5468.74,4229.37) ; U8.N15@5449.06,4217.03 ccw(c5449.06,4234.75) 5461.59,4222.22 ccw(c5474.12,4209.68) U8.N15@5456.4,4209.69 ; U8.N15@5449.06,4217.19 ccw(c5449.06,4235.29) 5461.86,4222.49 ccw(c5474.66,4209.68) U8.N15@5456.56,4209.69 ; U8.L15@5449.06,4288.43 v3(5468.74,4308.11) ; U8.L15@5449.06,4295.77 ccw(c5449.06,4313.49) 5461.59,4300.96 ccw(c5474.12,4288.43) U8.L15@5456.4,4288.43 ; U8.L15@5449.06,4295.93 ccw(c5449.06,4314.03) 5461.86,4301.23 ccw(c5474.66,4288.43) U8.L15@5456.56,4288.43 ; v1@5465,4805.5 cw(c5465,4798.1) 5470.23,4803.33 ; v1(5465,4815) 5458.56,4815 5488.43,4785.14 5488.43,4724.74 5488.43,4720 5488.43,4710 U8.A16@5488.43,4682.13 ; v1@5466.5,4814.97 ccw(c5484.84,4814.67) 5471.87,4801.7 ; v1@5470.5,4814.91 ccw(c5497.95,4814.44) 5478.54,4795.03 ; v1@5474.5,4814.84 ccw(c5511.07,4814.22) 5485.21,4788.36 ; U8.AF16@5483.12,3692.57 cw(c5470.32,3679.77) 5488.43,3679.77 cw(c5506.53,3679.77) U8.AF16@5493.73,3692.57 ; U8.A16@5483.12,4687.43 ccw(c5470.32,4700.23) 5488.43,4700.23 ccw(c5506.53,4700.23) U8.A16@5493.73,4687.43 ; U8.AF16@5483.23,3692.68 cw(c5470.7,3680.15) 5488.43,3680.15 cw(c5506.15,3680.15) U8.AF16@5493.62,3692.68 ; U8.A16@5483.23,4687.32 ccw(c5470.7,4699.85) 5488.43,4699.85 ccw(c5506.15,4699.85) U8.A16@5493.62,4687.32 ; U8.AF16@5488.43,3697.87 5488.43,3670 5488.43,3660 5488.43,3655.26 5488.43,3637.81 v1@5515.62,3610.62 ; U8.AA16@5488.43,3887.22 cw(c5488.43,3869.12) 5501.23,3881.92 cw(c5514.03,3894.72) U8.AA16@5495.93,3894.72 ; U8.AA16@5488.43,3887.38 cw(c5488.43,3869.66) 5500.96,3882.19 cw(c5513.49,3894.72) U8.AA16@5495.77,3894.72 ; U8.AA16@5488.43,3894.72 v3(5508.11,3875.04) ; U8.T16@5488.43,4084.07 cw(c5488.43,4065.97) 5501.23,4078.77 cw(c5514.03,4091.57) U8.T16@5495.93,4091.57 ; U8.T16@5488.43,4084.23 cw(c5488.43,4066.51) 5500.96,4079.04 cw(c5513.49,4091.57) U8.T16@5495.77,4091.57 ; U8.T16@5488.43,4091.57 v3(5508.11,4071.89) ; U8.P16@5488.43,4162.81 cw(c5488.43,4144.71) 5501.23,4157.51 cw(c5514.03,4170.32) U8.P16@5495.93,4170.32 ; U8.P16@5488.43,4162.97 cw(c5488.43,4145.25) 5500.96,4157.78 cw(c5513.49,4170.32) U8.P16@5495.77,4170.32 ; U8.P16@5488.43,4170.31 v3(5508.11,4150.63) ; U8.M16@5488.43,4249.06 v3(5508.11,4268.74) ; U8.M16@5488.43,4256.4 ccw(c5488.43,4274.12) 5500.96,4261.59 ccw(c5513.49,4249.06) U8.M16@5495.77,4249.06 ; U8.M16@5488.43,4256.56 ccw(c5488.43,4274.66) 5501.23,4261.86 ccw(c5514.03,4249.06) U8.M16@5495.93,4249.06 ; U8.F16@5488.43,4485.28 v3(5508.11,4504.96) ; U8.F16@5488.43,4492.62 ccw(c5488.43,4510.34) 5500.96,4497.81 ccw(c5513.49,4485.28) U8.F16@5495.77,4485.28 ; U8.F16@5488.43,4492.78 ccw(c5488.43,4510.88) 5501.23,4498.08 ccw(c5514.03,4485.28) U8.F16@5495.93,4485.28 ; 5497.91,3628.32 cw(c5479.59,3610) v1@5505.5,3610 ; 5500.89,3625.35 ccw(c5515,3639.46) v1@5515,3619.5 ; 5504.74,3621.49 cw(c5493.25,3610) v1@5509.5,3610 ; U8.U17@5527.8,4044.7 cw(c5527.8,4026.6) 5540.6,4039.4 cw(c5553.4,4052.2) U8.U17@5535.3,4052.2 ; U8.U17@5527.8,4044.86 cw(c5527.8,4027.14) 5540.33,4039.67 cw(c5552.86,4052.2) U8.U17@5535.14,4052.2 ; U8.U17@5527.8,4052.2 v3(5547.48,4032.52) ; U8.K17@5527.8,4327.8 v3(5547.48,4347.48) ; U8.K17@5527.8,4335.14 ccw(c5527.8,4352.86) 5540.33,4340.33 ccw(c5552.86,4327.8) U8.K17@5535.14,4327.8 ; U8.K17@5527.8,4335.3 ccw(c5527.8,4353.4) 5540.6,4340.6 ccw(c5553.4,4327.8) U8.K17@5535.3,4327.8 ; U8.AD18@5567.17,3769.27 cw(c5567.17,3751.55) 5579.7,3764.08 ; U8.AD18@5574.51,3776.61 ccw(c5592.23,3776.61) 5579.7,3764.08 ; v1(5594.19,3624.71) 5590.86,3628.04 5590.86,3636.2 5591.03,3636.2 5591.03,3655.26 5591.03,3660 5591.03,3670 5591.03,3736.73 ccw(c5552.35,3736.73) 5579.7,3764.08 ; U8.W19@5606.54,3965.96 cw(c5606.54,3947.86) 5619.34,3960.66 cw(c5632.14,3973.46) U8.W19@5614.04,3973.46 ; U8.W19@5606.54,3966.12 cw(c5606.54,3948.4) 5619.07,3960.93 cw(c5631.6,3973.46) U8.W19@5613.88,3973.46 ; U8.W19@5606.54,3973.46 v3(5626.22,3953.78) ; U8.P19@5606.54,4162.81 cw(c5606.54,4144.71) 5619.34,4157.51 cw(c5632.14,4170.31) U8.P19@5614.04,4170.31 ; U8.P19@5606.54,4162.97 cw(c5606.54,4145.25) 5619.07,4157.78 cw(c5631.6,4170.31) U8.P19@5613.88,4170.31 ; U8.P19@5606.54,4170.31 v3(5626.22,4150.63) ; U8.H19@5606.54,4406.54 v3(5626.22,4426.22) ; U8.H19@5606.54,4413.88 ccw(c5606.54,4431.6) 5619.07,4419.07 ccw(c5631.6,4406.54) U8.H19@5613.88,4406.54 ; U8.H19@5606.54,4414.04 ccw(c5606.54,4432.14) 5619.34,4419.34 ccw(c5632.14,4406.54) U8.H19@5614.04,4406.54 ; U8.C19@5606.54,4610.73 ccw(c5606.54,4628.45) 5619.07,4615.92 ; U8.C19@5613.88,4603.39 cw(c5631.6,4603.39) 5619.07,4615.92 ; v1(5631.86,4758.37) 5630.4,4756.91 5630.4,4724.74 5630.4,4720 5630.4,4710 5630.4,4643.27 cw(c5591.72,4643.27) 5619.07,4615.92 ; v1(5640.19,3175.04) 5665.04,3175.04 NT40.2@5670,3180 ; v1@5644.08,3171.15 cw(c5653.47,3161.76) 5653.47,3175.04 cw(c5653.47,3188.32) v1@5644.08,3178.93 ; U8.V20@5645.91,4005.33 cw(c5645.91,3987.23) 5658.71,4000.03 cw(c5671.51,4012.83) U8.V20@5653.41,4012.83 ; U8.V20@5645.91,4005.49 cw(c5645.91,3987.77) 5658.44,4000.3 cw(c5670.97,4012.83) U8.V20@5653.25,4012.83 ; U8.V20@5645.91,4012.83 v3(5665.59,3993.15) ; v1@5646.91,3168.32 cw(c5663.13,3152.11) 5663.13,3175.04 cw(c5663.13,3197.98) v1@5646.91,3181.76 ; 5659.23,3175.04 ccw(c5659.23,3186.27) NT40.2@5667.17,3178.33 ; 5661.45,3175.04 cw(c5661.45,3166.95) NT40.2@5667.17,3172.67 ; U8.AF21@5679.97,3692.57 cw(c5667.17,3679.77) 5685.28,3679.77 cw(c5703.38,3679.77) U8.AF21@5690.58,3692.57 ; U8.A21@5679.97,4687.43 ccw(c5667.17,4700.23) 5685.28,4700.23 ccw(c5703.38,4700.23) U8.A21@5690.58,4687.43 ; U8.AF21@5680.08,3692.68 cw(c5667.55,3680.15) 5685.28,3680.15 cw(c5703,3680.15) U8.AF21@5690.47,3692.68 ; U8.A21@5680.08,4687.32 ccw(c5667.55,4699.85) 5685.28,4699.85 ccw(c5703,4699.85) U8.A21@5690.47,4687.32 ; v1(5682.52,3603.71) 5682.52,3618.37 5685.28,3621.13 5685.28,3655.26 5685.28,3660 5685.28,3670 U8.AF21@5685.28,3697.87 ; U8.AA21@5685.28,3887.22 cw(c5685.28,3869.12) 5698.08,3881.92 cw(c5710.88,3894.72) U8.AA21@5692.78,3894.72 ; U8.AA21@5685.28,3887.38 cw(c5685.28,3869.66) 5697.81,3882.19 cw(c5710.34,3894.72) U8.AA21@5692.62,3894.72 ; U8.AA21@5685.28,3894.72 v3(5704.96,3875.04) ; U8.T21@5685.28,4084.07 cw(c5685.28,4065.97) 5698.08,4078.77 cw(c5710.88,4091.57) U8.T21@5692.78,4091.57 ; U8.T21@5685.28,4084.23 cw(c5685.28,4066.51) 5697.81,4079.04 cw(c5710.34,4091.57) U8.T21@5692.62,4091.57 ; U8.T21@5685.28,4091.57 v3(5704.96,4071.89) ; U8.L21@5685.28,4288.43 v3(5704.96,4308.11) ; U8.L21@5685.28,4295.77 ccw(c5685.28,4313.49) 5697.81,4300.96 ccw(c5710.34,4288.43) U8.L21@5692.62,4288.43 ; U8.L21@5685.28,4295.93 ccw(c5685.28,4314.03) 5698.08,4301.23 ccw(c5710.88,4288.43) U8.L21@5692.78,4288.43 ; U8.F21@5685.28,4485.28 v3(5704.96,4504.96) ; U8.F21@5685.28,4492.62 ccw(c5685.28,4510.34) 5697.81,4497.81 ccw(c5710.34,4485.28) U8.F21@5692.62,4485.28 ; U8.F21@5685.28,4492.78 ccw(c5685.28,4510.88) 5698.08,4498.08 ccw(c5710.88,4485.28) U8.F21@5692.78,4485.28 ; U8.A21@5685.28,4682.13 5685.28,4710 5685.28,4720 5685.28,4724.74 5685.28,4754.13 v1(5698.52,4767.37) ; U8.AD24@5803.39,3769.27 cw(c5803.39,3751.55) 5815.92,3764.08 ; U8.W24@5803.39,3966.12 cw(c5803.39,3948.4) 5815.92,3960.93 ; U8.P24@5803.39,4162.97 cw(c5803.39,4145.25) 5815.92,4157.78 ; U8.J24@5803.39,4374.51 ccw(c5803.39,4392.23) 5815.92,4379.7 ; U8.C24@5803.39,4610.73 ccw(c5803.39,4628.45) 5815.92,4615.92 ; U8.AD24@5810.73,3776.61 ccw(c5828.45,3776.61) 5815.92,3764.08 ; U8.W24@5810.73,3973.46 ccw(c5828.45,3973.46) 5815.92,3960.93 ; U8.P24@5810.73,4170.31 ccw(c5828.45,4170.31) 5815.92,4157.78 ; U8.J24@5810.73,4367.17 cw(c5828.45,4367.17) 5815.92,4379.7 ; U8.C24@5810.73,4603.39 cw(c5828.45,4603.39) 5815.92,4615.92 ; U8.AF26@5882.13,3705.22 ccw(c5882.13,3722.94) 5894.66,3710.41 ; U8.AA26@5882.13,3894.72 5910,3894.72 5920,3894.72 5972.23,3894.72 5986.72,3909.21 6010.79,3909.21 6015,3905 6015,3870 v1(6020,3865) ; U8.T26@5882.13,4091.57 5910,4091.57 5920,4091.57 5924.74,4091.57 5958.43,4091.57 5967.86,4082.14 v1(5967.86,4053.71) 6005.65,4091.5 6048.32,4091.5 6065.19,4108.37 6065.19,4142.71 6057.86,4150.04 5981.86,4150.04 5969.95,4150.03 5954.99,4150.01 5951.41,4146.43 5942.4,4146.43 ; U8.L26@5882.13,4288.43 5910,4288.43 5920,4288.43 5924.74,4288.43 5944.81,4288.42 v1(5993.52,4239.71) ; U8.F26@5882.13,4485.28 5910,4485.28 5920,4485.28 5924.74,4485.28 ; U8.A26@5882.13,4674.78 cw(c5882.13,4657.06) 5894.66,4669.59 ; v1(5882.52,3578.37) 5882.52,3582.52 5936.02,3636.02 5936.02,3668.94 5945,3677.91 5945,3706.69 5929.95,3721.74 5922.01,3721.74 ccw(c5922.01,3683.06) 5894.66,3710.41 ; v1@5882.52,3587.87 ccw(c5882.52,3600.79) 5891.66,3591.66 ; U8.AA26@5887.32,3889.53 cw(c5899.85,3877) 5899.85,3894.72 cw(c5899.85,3912.45) U8.AA26@5887.32,3899.92 ; U8.T26@5887.32,4086.38 cw(c5899.85,4073.85) 5899.85,4091.57 cw(c5899.85,4109.3) U8.T26@5887.32,4096.77 ; U8.L26@5887.32,4283.23 cw(c5899.85,4270.7) 5899.85,4288.43 cw(c5899.85,4306.15) U8.L26@5887.32,4293.62 ; U8.F26@5887.32,4480.08 cw(c5899.85,4467.55) 5899.85,4485.28 cw(c5899.85,4503) U8.F26@5887.32,4490.47 ; U8.AA26@5887.43,3889.42 cw(c5900.23,3876.62) 5900.23,3894.72 cw(c5900.23,3912.83) U8.AA26@5887.43,3900.03 ; U8.T26@5887.43,4086.27 cw(c5900.23,4073.47) 5900.23,4091.57 cw(c5900.23,4109.68) U8.T26@5887.43,4096.88 ; U8.L26@5887.43,4283.12 cw(c5900.23,4270.32) 5900.23,4288.43 cw(c5900.23,4306.53) U8.L26@5887.43,4293.73 ; U8.F26@5887.43,4479.97 cw(c5900.23,4467.17) 5900.23,4485.28 cw(c5900.23,4503.38) U8.F26@5887.43,4490.58 ; v1@5888.02,3578.37 cw(c5911.32,3578.37) 5894.85,3594.85 ; U8.AF26@5889.47,3697.87 cw(c5907.2,3697.87) 5894.66,3710.41 ; U8.A26@5889.47,4682.13 ccw(c5907.2,4682.13) 5894.66,4669.59 ; v1@5892.02,3578.37 cw(c5924.98,3578.37) 5901.68,3601.68 ; 5924.74,4658.26 5940.52,4658.26 ; 5932.82,4485.28 cw(c5932.82,4460.97) v1@5952.15,4475.71 ; 5933.22,4627.25 ccw(c5933.22,4653.67) v1@5953.61,4636.87 ; 5940.9,4485.28 cw(c5940.9,4467.13) v1@5955.33,4478.13 ; 5941.7,4627.25 ccw(c5941.7,4646.69) v1@5956.7,4634.33 ; v1@5948.97,4473.28 ccw(c5924.74,4454.81) 5924.74,4485.28 ; v1@5950.52,4639.41 cw(c5924.74,4660.65) 5924.74,4627.25 ; v1(5956.52,4479.04) 5950.29,4485.28 5924.74,4485.28 ; v1(5957.86,4633.37) 5955.65,4631.17 5954.65,4631.17 5954.65,4630.91 5950.98,4627.25 5924.74,4627.25 ; v1@5958.47,4735.99 cw(c5942.26,4719.77) 5965.19,4719.77 cw(c5988.13,4719.77) v1@5971.91,4735.99 ; v1@5961.14,4060.43 ccw(c5944.92,4076.64) 5967.86,4076.64 ccw(c5990.79,4076.64) v1@5974.57,4060.43 ; v1@5961.3,4738.82 cw(c5951.91,4729.43) 5965.19,4729.43 cw(c5978.47,4729.43) v1@5969.08,4738.82 ; v1(5961.52,3658.37) 5961.52,3712.79 5946.19,3728.13 5946.19,3735.3 5928.74,3752.75 5924.74,3752.75 5920,3752.75 5910,3752.75 5843.27,3752.75 ; v1@5963.97,4057.6 ccw(c5954.58,4066.99) 5967.86,4066.99 ccw(c5981.14,4066.99) v1@5971.75,4057.6 ; v1(5965.19,4742.71) 5965.19,4680.19 5943.26,4658.26 5922.01,4658.26 cw(c5922.01,4696.94) 5894.66,4669.59 ; v1@5967.86,4059.21 ccw(c5967.86,4072.49) 5977.25,4063.1 ccw(c5986.64,4053.71) v1@5973.36,4053.71 ; v1@5967.86,4063.21 ccw(c5967.86,4086.14) 5984.07,4069.93 ccw(c6000.29,4053.71) v1@5977.36,4053.71 ; v1@5982.31,4369.19 ccw(c5977.14,4377.81) 5987.19,4377.81 ; v1@5984.02,4239.71 ccw(c5961.09,4239.71) 5977.31,4255.93 ccw(c5993.52,4272.14) v1@5993.52,4249.21 ; v1(5987.19,4361.04) 5987.19,4377.81 ; v1@5988.02,4239.71 ccw(c5974.75,4239.71) 5984.14,4249.1 ccw(c5993.52,4258.49) v1@5993.52,4245.21 ; v1@5992.07,4369.19 cw(c5997.24,4377.81) 5987.19,4377.81 ; v1@6013.28,3871.72 ccw(c6009.14,3875.86) 6015,3875.86 ; 6015,3880.69 ccw(c6035.69,3880.69) v1@6021.06,3866.06 ; 6015,3890.35 ccw(c6045.35,3890.35) v1@6023.89,3868.89 ; 6015,3900.01 ccw(c6055.01,3900.01) v1@6026.72,3871.72 ; 6139.86,3828.04 6083.52,3884.37 6069.79,3884.37 6048.02,3906.15 6048.02,3932.87 6037.75,3943.15 5961.05,3943.15 5957.77,3939.87 5943.28,3939.87 5933.55,3949.6 5920,3949.6 5910,3949.6 5843.27,3949.6 cw(c5843.27,3988.28) 5815.92,3960.93 ; U13.12@6145.93,3824.3 ccw(c6139.86,3821.14) 6139.86,3827.99 ; U13.12@6145.93,3831.68 cw(c6139.86,3834.84) 6139.86,3827.99 ; U13.12@6170.59,3827.99 6139.86,3827.99 ; v1(6218.52,3809.04) v1@6218.52,3817.66 ; 4840,3718.47 4840,3725 ; 4840,3718.47 4843.26,3721.74 ; 4840,3725 4840,3750 4842.75,3752.75 4860,3752.75 4870,3752.75 4936.73,3752.75 ; 4840,3725 4843.26,3721.74 ; 4843.26,3721.74 4857.99,3721.74 cw(c4857.99,3683.06) 4885.34,3710.41 ; 4936.73,3752.75 ccw(c4936.73,3791.43) 4964.08,3764.08 ; 4936.73,3752.75 ccw(c4936.73,3791.43) 4964.08,3764.08 ; 4936.73,4627.25 cw(c4936.73,4588.57) 4964.08,4615.92 ; 4936.73,4627.25 cw(c4936.73,4588.57) 4964.08,4615.92 ; 5087.84,3887.84 ccw(c5100.65,3875.04) 5082.54,3875.04 cw(c5100.65,3875.04) 5087.84,3887.84 ; 5087.84,3887.84 cw(c5075.04,3900.65) 5075.04,3882.54 ccw(c5075.04,3900.65) 5087.84,3887.84 ; 5087.84,4084.69 cw(c5075.04,4097.5) 5075.04,4079.39 ccw(c5075.04,4097.5) 5087.84,4084.69 ; 5087.84,4084.69 ccw(c5100.65,4071.89) 5082.54,4071.89 cw(c5100.65,4071.89) 5087.84,4084.69 ; 5087.84,4295.31 cw(c5100.65,4308.11) 5082.54,4308.11 ccw(c5100.65,4308.11) 5087.84,4295.31 ; 5087.84,4295.31 ccw(c5075.04,4282.5) 5075.04,4300.61 cw(c5075.04,4282.5) 5087.84,4295.31 ; 5087.84,4492.16 cw(c5100.65,4504.96) 5082.54,4504.96 ccw(c5100.65,4504.96) 5087.84,4492.16 ; 5087.84,4492.16 ccw(c5075.04,4479.35) 5075.04,4497.46 cw(c5075.04,4479.35) 5087.84,4492.16 ; 5166.58,3966.58 ccw(c5179.39,3953.78) 5161.28,3953.78 cw(c5179.39,3953.78) 5166.58,3966.58 ; 5166.58,3966.58 cw(c5153.78,3979.39) 5153.78,3961.28 ccw(c5153.78,3979.39) 5166.58,3966.58 ; 5166.58,4216.57 cw(c5179.39,4229.37) 5161.28,4229.37 ccw(c5179.39,4229.37) 5166.58,4216.57 ; 5166.58,4216.57 ccw(c5153.78,4203.76) 5153.78,4221.87 cw(c5153.78,4203.76) 5166.58,4216.57 ; 5166.58,4413.42 cw(c5179.39,4426.22) 5161.28,4426.22 ccw(c5179.39,4426.22) 5166.58,4413.42 ; 5166.58,4413.42 ccw(c5153.78,4400.61) 5153.78,4418.72 cw(c5153.78,4400.61) 5166.58,4413.42 ; 5245.32,4045.32 cw(c5232.52,4058.13) 5232.52,4040.02 ccw(c5232.52,4058.13) 5245.32,4045.32 ; 5245.32,4045.32 ccw(c5258.13,4032.52) 5240.02,4032.52 cw(c5258.13,4032.52) 5245.32,4045.32 ; 5245.32,4334.68 cw(c5258.13,4347.48) 5240.02,4347.48 ccw(c5258.13,4347.48) 5245.32,4334.68 ; 5245.32,4334.68 ccw(c5232.52,4321.87) 5232.52,4339.98 cw(c5232.52,4321.87) 5245.32,4334.68 ; 5284.69,3887.84 ccw(c5297.5,3875.04) 5279.39,3875.04 cw(c5297.5,3875.04) 5284.69,3887.84 ; 5284.69,3887.84 cw(c5271.89,3900.65) 5271.89,3882.54 ccw(c5271.89,3900.65) 5284.69,3887.84 ; 5284.69,4124.06 cw(c5271.89,4136.87) 5271.89,4118.76 ccw(c5271.89,4136.87) 5284.69,4124.06 ; 5284.69,4124.06 ccw(c5297.5,4111.26) 5279.39,4111.26 cw(c5297.5,4111.26) 5284.69,4124.06 ; 5284.69,4216.57 cw(c5297.5,4229.37) 5279.39,4229.37 ccw(c5297.5,4229.37) 5284.69,4216.57 ; 5284.69,4216.57 ccw(c5271.89,4203.76) 5271.89,4221.87 cw(c5271.89,4203.76) 5284.69,4216.57 ; 5284.69,4295.31 cw(c5297.5,4308.11) 5279.39,4308.11 ccw(c5297.5,4308.11) 5284.69,4295.31 ; 5284.69,4295.31 ccw(c5271.89,4282.5) 5271.89,4300.61 cw(c5271.89,4282.5) 5284.69,4295.31 ; 5284.69,4492.16 cw(c5297.5,4504.96) 5279.39,4504.96 ccw(c5297.5,4504.96) 5284.69,4492.16 ; 5284.69,4492.16 ccw(c5271.89,4479.35) 5271.89,4497.46 cw(c5271.89,4479.35) 5284.69,4492.16 ; 5324.06,4084.69 cw(c5311.26,4097.5) 5311.26,4079.39 ccw(c5311.26,4097.5) 5324.06,4084.69 ; 5324.06,4084.69 ccw(c5336.87,4071.89) 5318.76,4071.89 cw(c5336.87,4071.89) 5324.06,4084.69 ; 5324.06,4163.43 cw(c5311.26,4176.24) 5311.26,4158.13 ccw(c5311.26,4176.24) 5324.06,4163.43 ; 5324.06,4163.43 ccw(c5336.87,4150.63) 5318.76,4150.63 cw(c5336.87,4150.63) 5324.06,4163.43 ; 5324.06,4255.94 cw(c5336.87,4268.74) 5318.76,4268.74 ccw(c5336.87,4268.74) 5324.06,4255.94 ; 5324.06,4255.94 ccw(c5311.26,4243.13) 5311.26,4261.24 cw(c5311.26,4243.13) 5324.06,4255.94 ; 5346.46,3651.37 5346.45,3655.26 5346.45,3660 ; 5346.45,3651.37 5346.45,3660 ; 5346.45,3660 5346.45,3670 5346.45,3736.73 cw(c5385.13,3736.73) 5357.78,3764.08 ; 5363.43,4045.32 cw(c5350.63,4058.13) 5350.63,4040.02 ccw(c5350.63,4058.13) 5363.43,4045.32 ; 5363.43,4045.32 ccw(c5376.24,4032.52) 5358.13,4032.52 cw(c5376.24,4032.52) 5363.43,4045.32 ; 5363.43,4124.06 cw(c5350.63,4136.87) 5350.63,4118.76 ccw(c5350.63,4136.87) 5363.43,4124.06 ; 5363.43,4124.06 ccw(c5376.24,4111.26) 5358.13,4111.26 cw(c5376.24,4111.26) 5363.43,4124.06 ; 5363.43,4295.31 cw(c5376.24,4308.11) 5358.13,4308.11 ccw(c5376.24,4308.11) 5363.43,4295.31 ; 5363.43,4295.31 ccw(c5350.63,4282.5) 5350.63,4300.61 cw(c5350.63,4282.5) 5363.43,4295.31 ; 5416.57,3966.58 cw(c5403.76,3953.78) 5421.87,3953.78 ccw(c5403.76,3953.78) 5416.57,3966.58 ; 5416.57,3966.58 ccw(c5429.37,3979.39) 5429.37,3961.28 cw(c5429.37,3979.39) 5416.57,3966.58 ; 5416.57,4084.69 cw(c5403.76,4071.89) 5421.87,4071.89 ccw(c5403.76,4071.89) 5416.57,4084.69 ; 5416.57,4084.69 ccw(c5429.37,4097.5) 5429.37,4079.39 cw(c5429.37,4097.5) 5416.57,4084.69 ; 5416.57,4255.94 cw(c5429.37,4243.13) 5429.37,4261.24 ccw(c5429.37,4243.13) 5416.57,4255.94 ; 5416.57,4255.94 ccw(c5403.76,4268.74) 5421.87,4268.74 cw(c5403.76,4268.74) 5416.57,4255.94 ; 5416.57,4413.42 cw(c5429.37,4400.61) 5429.37,4418.72 ccw(c5429.37,4400.61) 5416.57,4413.42 ; 5416.57,4413.42 ccw(c5403.76,4426.22) 5421.87,4426.22 cw(c5403.76,4426.22) 5416.57,4413.42 ; 5455.94,4124.06 cw(c5443.13,4111.26) 5461.24,4111.26 ccw(c5443.13,4111.26) 5455.94,4124.06 ; 5455.94,4124.06 ccw(c5468.74,4136.87) 5468.74,4118.76 cw(c5468.74,4136.87) 5455.94,4124.06 ; 5455.94,4216.57 cw(c5468.74,4203.76) 5468.74,4221.87 ccw(c5468.74,4203.76) 5455.94,4216.57 ; 5455.94,4216.57 ccw(c5443.13,4229.37) 5461.24,4229.37 cw(c5443.13,4229.37) 5455.94,4216.57 ; 5455.94,4295.31 cw(c5468.74,4282.5) 5468.74,4300.61 ccw(c5468.74,4282.5) 5455.94,4295.31 ; 5455.94,4295.31 ccw(c5443.13,4308.11) 5461.24,4308.11 cw(c5443.13,4308.11) 5455.94,4295.31 ; 5495.31,3887.84 cw(c5482.5,3875.04) 5500.61,3875.04 ccw(c5482.5,3875.04) 5495.31,3887.84 ; 5495.31,3887.84 ccw(c5508.11,3900.65) 5508.11,3882.54 cw(c5508.11,3900.65) 5495.31,3887.84 ; 5495.31,4084.69 cw(c5482.5,4071.89) 5500.61,4071.89 ccw(c5482.5,4071.89) 5495.31,4084.69 ; 5495.31,4084.69 ccw(c5508.11,4097.5) 5508.11,4079.39 cw(c5508.11,4097.5) 5495.31,4084.69 ; 5495.31,4163.43 cw(c5482.5,4150.63) 5500.61,4150.63 ccw(c5482.5,4150.63) 5495.31,4163.43 ; 5495.31,4163.43 ccw(c5508.11,4176.24) 5508.11,4158.13 cw(c5508.11,4176.24) 5495.31,4163.43 ; 5495.31,4255.94 cw(c5508.11,4243.13) 5508.11,4261.24 ccw(c5508.11,4243.13) 5495.31,4255.94 ; 5495.31,4255.94 ccw(c5482.5,4268.74) 5500.61,4268.74 cw(c5482.5,4268.74) 5495.31,4255.94 ; 5495.31,4492.16 cw(c5508.11,4479.35) 5508.11,4497.46 ccw(c5508.11,4479.35) 5495.31,4492.16 ; 5495.31,4492.16 ccw(c5482.5,4504.96) 5500.61,4504.96 cw(c5482.5,4504.96) 5495.31,4492.16 ; 5534.68,4045.32 cw(c5521.87,4032.52) 5539.98,4032.52 ccw(c5521.87,4032.52) 5534.68,4045.32 ; 5534.68,4045.32 ccw(c5547.48,4058.13) 5547.48,4040.02 cw(c5547.48,4058.13) 5534.68,4045.32 ; 5534.68,4334.68 cw(c5547.48,4321.87) 5547.48,4339.98 ccw(c5547.48,4321.87) 5534.68,4334.68 ; 5534.68,4334.68 ccw(c5521.87,4347.48) 5539.98,4347.48 cw(c5521.87,4347.48) 5534.68,4334.68 ; 5613.42,3966.58 cw(c5600.61,3953.78) 5618.72,3953.78 ccw(c5600.61,3953.78) 5613.42,3966.58 ; 5613.42,3966.58 ccw(c5626.22,3979.39) 5626.22,3961.28 cw(c5626.22,3979.39) 5613.42,3966.58 ; 5613.42,4163.43 cw(c5600.61,4150.63) 5618.72,4150.63 ccw(c5600.61,4150.63) 5613.42,4163.43 ; 5613.42,4163.43 ccw(c5626.22,4176.24) 5626.22,4158.13 cw(c5626.22,4176.24) 5613.42,4163.43 ; 5613.42,4413.42 cw(c5626.22,4400.61) 5626.22,4418.72 ccw(c5626.22,4400.61) 5613.42,4413.42 ; 5613.42,4413.42 ccw(c5600.61,4426.22) 5618.72,4426.22 cw(c5600.61,4426.22) 5613.42,4413.42 ; 5652.79,4005.95 cw(c5639.98,3993.15) 5658.09,3993.15 ccw(c5639.98,3993.15) 5652.79,4005.95 ; 5652.79,4005.95 ccw(c5665.59,4018.76) 5665.59,4000.65 cw(c5665.59,4018.76) 5652.79,4005.95 ; 5692.16,3887.84 cw(c5679.35,3875.04) 5697.46,3875.04 ccw(c5679.35,3875.04) 5692.16,3887.84 ; 5692.16,3887.84 ccw(c5704.96,3900.65) 5704.96,3882.54 cw(c5704.96,3900.65) 5692.16,3887.84 ; 5692.16,4084.69 cw(c5679.35,4071.89) 5697.46,4071.89 ccw(c5679.35,4071.89) 5692.16,4084.69 ; 5692.16,4084.69 ccw(c5704.96,4097.5) 5704.96,4079.39 cw(c5704.96,4097.5) 5692.16,4084.69 ; 5692.16,4295.31 cw(c5704.96,4282.5) 5704.96,4300.61 ccw(c5704.96,4282.5) 5692.16,4295.31 ; 5692.16,4295.31 ccw(c5679.35,4308.11) 5697.46,4308.11 cw(c5679.35,4308.11) 5692.16,4295.31 ; 5692.16,4492.16 cw(c5704.96,4479.35) 5704.96,4497.46 ccw(c5704.96,4479.35) 5692.16,4492.16 ; 5692.16,4492.16 ccw(c5679.35,4504.96) 5697.46,4504.96 cw(c5679.35,4504.96) 5692.16,4492.16 ; 5815.92,3764.08 ccw(c5843.27,3791.43) 5843.27,3752.75 ; 5815.92,3764.08 ccw(c5843.27,3791.43) 5843.27,3752.75 ; 5815.92,4157.78 ccw(c5843.27,4185.13) 5843.27,4146.45 5910,4146.45 5920,4146.45 5923.52,4146.45 5936.24,4146.43 ; 5815.92,4379.7 cw(c5843.27,4352.35) 5843.27,4391.03 5910,4391.03 5920,4391.03 5924.74,4391.03 5973.97,4391.03 5987.19,4377.81 ; 5815.92,4615.92 cw(c5843.27,4588.57) 5843.27,4627.25 ; 5815.92,4615.92 cw(c5843.27,4588.57) 5843.27,4627.25 ; 5843.27,4627.25 5910,4627.25 5920,4627.25 5924.74,4627.25 ; 5936.24,4146.43 5942.4,4146.43 ; 5936.24,4146.43 5942.39,4146.42
  Top Layer w5: 5220,730 5255,765 5410,765 5457.5,812.5 5457.5,1124.16 5349,1232.66 5349,2101.88 5417.62,2170.5 5990.5,2170.5 6005,2185 6005,2208.37 ; 5510,726.82 5490.5,746.32 5490.5,1137.83 5382,1246.33 5382,2088.21 5431.29,2137.5 6102.5,2137.5 6140,2175 6140,2208.37 ; 5523.5,915 5523.5,995 ; 5732.65,802.5 5725,802.5 ; 5850,730 5850,740 5787.5,802.5 5725,802.5 ; 6251,2216 ccw(c6240.19,2226.81) U61.36@6255.47,2226.81 ; U61.36@6258.97,2240 6258.97,2223.97 6139.5,2104.5 5444.96,2104.5 5415,2074.54 5415,1260 5523.5,1151.5 5523.5,995 ; 5523.5,995 5523.5,803.32 5524.32,802.5 5725,802.5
